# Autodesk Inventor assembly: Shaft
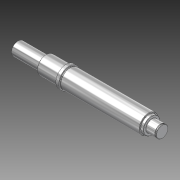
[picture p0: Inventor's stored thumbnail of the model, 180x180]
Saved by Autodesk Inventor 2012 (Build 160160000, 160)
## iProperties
Created: 2007-07
Part Number: Shaft
Document SubType Name: Assembly
Designer: Designer
ClientObjectVersion: 1
Author: Designer
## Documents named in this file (2)
- C:\CMU\Datasets\Session 6\Cluster Ex 1\Workspaces\Workspace\GearBox-A\Design Accelerator\Shaft2.iam
- C:\CMU\Datasets\Session 6\Cluster Ex 1\Workspaces\Workspace\GearBox-A\Design Accelerator\Shaft2.ipt
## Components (1 placed, 1 different names)
1. Shaft:1
